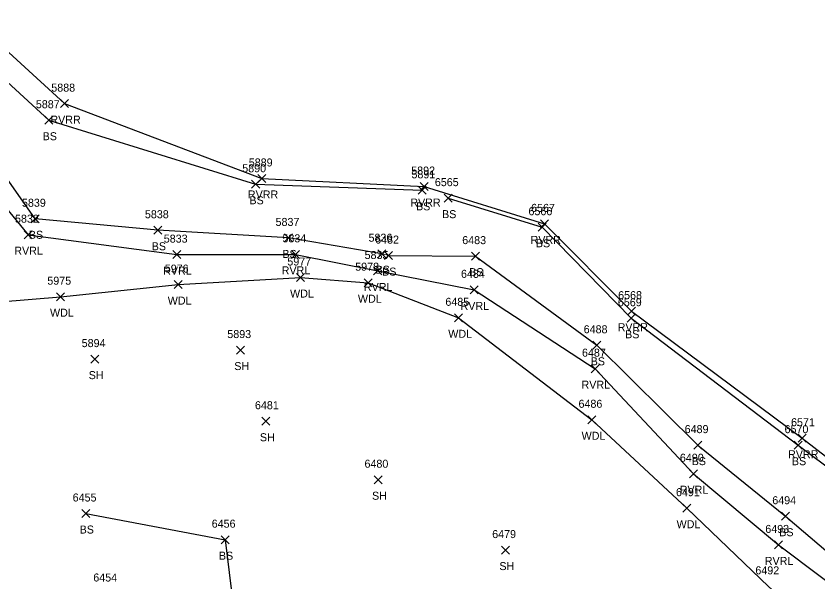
# Model space of a CAD drawing. Extents: x 1588028 to 1589597, y 137576 to 138176.
# Drawn here: x 1588574.1 to 1588774.4, y 138029.2 to 138170.6 of the extents above; entities that cross this region are included whole.
import ezdxf

# ---------------------------------------------------------------- set-up
doc = ezdxf.new("R2010")
doc.units = 0
for name, color, linetype in [('L_A', 7, 'Continuous'), ('L_I', 7, 'Continuous'), ('L_TIC', 7, 'Continuous'), ('LAWA', 7, 'Continuous'), ('LAWE', 7, 'Continuous'), ('LELB', 7, 'Continuous')]:
    doc.layers.add(name, color=color, linetype=linetype)

msp = doc.modelspace()

# ---------------------------------------------------------------- linework, layer by layer
at = {"layer": 'L_TIC'}
for points in [[(1588585.16, 138147.71), (1588587.16, 138149.71)], [(1588587.16, 138147.71), (1588585.16, 138149.71)], [(1588581.3, 138143.56), (1588583.3, 138145.56)], [(1588583.3, 138143.56), (1588581.3, 138145.56)], [(1588634.49, 138129.01), (1588636.49, 138131.01)], [(1588636.49, 138129.01), (1588634.49, 138131.01)], [(1588632.94, 138127.56), (1588634.94, 138129.56)], [(1588634.94, 138127.56), (1588632.94, 138129.56)], [(1588674.55, 138126.05), (1588676.55, 138128.05)], [(1588676.55, 138126.05), (1588674.55, 138128.05)], [(1588675.05, 138126.99), (1588677.05, 138128.99)], [(1588677.05, 138126.99), (1588675.05, 138128.99)], [(1588681.05, 138124.09), (1588683.05, 138126.09)], [(1588683.05, 138124.09), (1588681.05, 138126.09)], [(1588577.85, 138118.94), (1588579.85, 138120.94)], [(1588579.85, 138118.94), (1588577.85, 138120.94)], [(1588608.54, 138116.07), (1588610.54, 138118.07)], [(1588610.54, 138116.07), (1588608.54, 138118.07)], [(1588704.48, 138116.82), (1588706.48, 138118.82)], [(1588706.48, 138116.82), (1588704.48, 138118.82)], [(1588705.09, 138117.66), (1588707.09, 138119.66)], [(1588707.09, 138117.66), (1588705.09, 138119.66)], [(1588576.1, 138114.96), (1588578.1, 138116.96)], [(1588578.1, 138114.96), (1588576.1, 138116.96)], [(1588641.17, 138114.15), (1588643.17, 138116.15)], [(1588643.17, 138114.15), (1588641.17, 138116.15)], [(1588613.25, 138109.98), (1588615.25, 138111.98)], [(1588615.25, 138109.98), (1588613.25, 138111.98)], [(1588642.88, 138110.05), (1588644.88, 138112.05)], [(1588644.88, 138110.05), (1588642.88, 138112.05)], [(1588664.44, 138110.2), (1588666.44, 138112.2)], [(1588666.44, 138110.2), (1588664.44, 138112.2)], [(1588666.09, 138109.74), (1588668.09, 138111.74)], [(1588668.09, 138109.74), (1588666.09, 138111.74)], [(1588687.84, 138109.6), (1588689.84, 138111.6)], [(1588689.84, 138109.6), (1588687.84, 138111.6)], [(1588644.11, 138104.26), (1588646.11, 138106.26)], [(1588646.11, 138104.26), (1588644.11, 138106.26)], [(1588663.41, 138105.89), (1588665.41, 138107.89)], [(1588665.41, 138105.89), (1588663.41, 138107.89)], [(1588613.56, 138102.49), (1588615.56, 138104.49)], [(1588615.56, 138102.49), (1588613.56, 138104.49)], [(1588661.06, 138102.96), (1588663.06, 138104.96)], [(1588663.06, 138102.96), (1588661.06, 138104.96)], [(1588687.53, 138101.18), (1588689.53, 138103.18)], [(1588689.53, 138101.18), (1588687.53, 138103.18)], [(1588584.17, 138099.47), (1588586.17, 138101.47)], [(1588586.17, 138099.47), (1588584.17, 138101.47)], [(1588683.62, 138094.19), (1588685.62, 138096.19)], [(1588685.62, 138094.19), (1588683.62, 138096.19)], [(1588726.76, 138094.08), (1588728.76, 138096.08)], [(1588728.76, 138094.08), (1588726.76, 138096.08)], [(1588726.82, 138095.85), (1588728.82, 138097.85)], [(1588728.82, 138095.85), (1588726.82, 138097.85)], [(1588629.12, 138086.13), (1588631.12, 138088.13)], [(1588631.12, 138086.13), (1588629.12, 138088.13)], [(1588718.17, 138087.33), (1588720.17, 138089.33)], [(1588720.17, 138087.33), (1588718.17, 138089.33)], [(1588592.75, 138083.87), (1588594.75, 138085.87)], [(1588594.75, 138083.87), (1588592.75, 138085.87)], [(1588717.75, 138081.48), (1588719.75, 138083.48)], [(1588719.75, 138081.48), (1588717.75, 138083.48)], [(1588635.5, 138068.35), (1588637.5, 138070.35)], [(1588637.5, 138068.35), (1588635.5, 138070.35)], [(1588716.93, 138068.71), (1588718.93, 138070.71)], [(1588718.93, 138068.71), (1588716.93, 138070.71)], [(1588769.39, 138064.1), (1588771.39, 138066.1)], [(1588771.39, 138064.1), (1588769.39, 138066.1)], [(1588743.4, 138062.38), (1588745.4, 138064.38)], [(1588745.4, 138062.38), (1588743.4, 138064.38)], [(1588768.43, 138062.36), (1588770.43, 138064.36)], [(1588770.43, 138062.36), (1588768.43, 138064.36)], [(1588742.28, 138055.23), (1588744.28, 138057.23)], [(1588744.28, 138055.23), (1588742.28, 138057.23)], [(1588663.51, 138053.73), (1588665.51, 138055.73)], [(1588665.51, 138053.73), (1588663.51, 138055.73)], [(1588740.65, 138046.62), (1588742.65, 138048.62)], [(1588742.65, 138046.62), (1588740.65, 138048.62)], [(1588590.54, 138045.29), (1588592.54, 138047.29)], [(1588592.54, 138045.29), (1588590.54, 138047.29)], [(1588765.27, 138044.61), (1588767.27, 138046.61)], [(1588767.27, 138044.61), (1588765.27, 138046.61)], [(1588625.32, 138038.75), (1588627.32, 138040.75)], [(1588627.32, 138038.75), (1588625.32, 138040.75)], [(1588695.32, 138036.15), (1588697.32, 138038.15)], [(1588697.32, 138036.15), (1588695.32, 138038.15)], [(1588763.53, 138037.44), (1588765.53, 138039.44)], [(1588765.53, 138037.44), (1588763.53, 138039.44)]]:
    msp.add_lwpolyline(points, dxfattribs=at)
at = {"layer": 'LAWA'}
msp.add_lwpolyline([(1588438.89, 138034.8), (1588460.15, 138038.23), (1588480.55, 138035.11), (1588505.29, 138026.54), (1588523.98, 138028.49), (1588536.66, 138053.55), (1588553.84, 138097.83), (1588585.17, 138100.47), (1588614.56, 138103.49), (1588645.11, 138105.26), (1588662.06, 138103.96), (1588684.62, 138095.19), (1588717.93, 138069.71), (1588741.65, 138047.62), (1588762.05, 138028.09), (1588788.28, 138004.54)], dxfattribs=at)
at = {"layer": 'LAWE'}
for points in [[(1588434.56, 138062.89), (1588458.47, 138076.79), (1588495.54, 138110.89), (1588517.72, 138151.17), (1588540.38, 138168.38), (1588562.32, 138170.6), (1588586.16, 138148.71), (1588635.49, 138130.01), (1588676.05, 138127.99), (1588706.09, 138118.66), (1588727.82, 138096.85), (1588770.39, 138065.1), (1588798.8, 138043.18), (1588827.56, 138018.04), (1588869.93, 137975.12), (1588899.99, 137936.94), (1588912.08, 137921.5), (1588926.82, 137898.29), (1588932.86, 137884.09), (1588938.83, 137878.76)], [(1588441.02, 138044.54), (1588465.05, 138060.11), (1588492.43, 138083.39), (1588521.86, 138113.88), (1588530.72, 138143.54), (1588545.57, 138151.23), (1588554.85, 138142.99), (1588577.1, 138115.96), (1588614.25, 138110.98), (1588643.88, 138111.05), (1588664.41, 138106.89), (1588688.53, 138102.18), (1588718.75, 138082.48), (1588743.28, 138056.23), (1588764.53, 138038.44), (1588797.04, 138013.98), (1588814.47, 138001.04), (1588852.47, 137959.37), (1588883.95, 137928.09), (1588897.47, 137912.79), (1588913.44, 137894.45), (1588920.69, 137884.16), (1588921.99, 137878.45)]]:
    msp.add_lwpolyline(points, dxfattribs=at)
at = {"layer": 'LELB'}
for points in [[(1588436.71, 138060.38), (1588458.88, 138076.1), (1588497.26, 138109.57), (1588518.14, 138150.78), (1588541.4, 138166.66), (1588559.34, 138165.64), (1588582.3, 138144.56), (1588633.94, 138128.56), (1588675.55, 138127.05)], [(1588665.44, 138111.2), (1588642.17, 138115.15), (1588609.54, 138117.07), (1588578.85, 138119.94), (1588562.88, 138142.65), (1588547.64, 138155.17), (1588533.27, 138148.8), (1588529.69, 138143.67), (1588525.97, 138129.22), (1588517.34, 138113.35), (1588491.08, 138084.67), (1588470.51, 138067.55), (1588448.25, 138052.11)], [(1588682.05, 138125.09), (1588705.48, 138117.82), (1588727.76, 138095.08), (1588769.43, 138063.36), (1588798.46, 138041.61), (1588826.19, 138016.5), (1588867.28, 137972.84), (1588898.61, 137935.76), (1588911.42, 137921.16), (1588925.66, 137898.09), (1588931.8, 137883.5), (1588937.54, 137876.95)], [(1588667.09, 138110.74), (1588688.84, 138110.6), (1588719.17, 138088.33), (1588744.4, 138063.38), (1588766.27, 138045.61), (1588798.27, 138018.43), (1588815.99, 138001.93), (1588854.1, 137960.89), (1588885.58, 137929.53), (1588899.45, 137912.94)], [(1588591.54, 138046.29), (1588626.32, 138039.75), (1588630.34, 138007.04), (1588626.86, 137991.11), (1588639.77, 137986.11), (1588660.41, 138007.02), (1588678.67, 138013.51), (1588710.59, 137997.46), (1588735.69, 137986.71)]]:
    msp.add_lwpolyline(points, dxfattribs=at)

# ---------------------------------------------------------------- texts
at = {"layer": 'L_A'}
for s, p in [('RVRR', (1588582.67, 138143.71)), ('BS', (1588580.74, 138139.56)), ('RVRR', (1588632, 138125.01)), ('BS', (1588632.38, 138123.56)), ('RVRR', (1588672.56, 138122.99)), ('BS', (1588673.99, 138122.05)), ('BS', (1588680.49, 138120.09)), ('BS', (1588577.29, 138114.94)), ('BS', (1588607.98, 138112.07)), ('RVRR', (1588702.6, 138113.66)), ('BS', (1588703.92, 138112.82)), ('RVRL', (1588573.66, 138110.96)), ('BS', (1588640.61, 138110.15)), ('RVRL', (1588610.82, 138105.98)), ('RVRL', (1588640.44, 138106.05)), ('BS', (1588663.88, 138106.2)), ('BS', (1588665.53, 138105.74)), ('BS', (1588687.28, 138105.6)), ('WDL', (1588642.53, 138100.26)), ('RVRL', (1588660.97, 138101.89)), ('WDL', (1588611.98, 138098.49)), ('WDL', (1588659.48, 138098.96)), ('RVRL', (1588685.1, 138097.18)), ('WDL', (1588582.58, 138095.47)), ('WDL', (1588682.04, 138090.19)), ('RVRR', (1588724.34, 138091.85)), ('BS', (1588726.2, 138090.08)), ('SH', (1588628.6, 138082.13)), ('BS', (1588717.61, 138083.33)), ('SH', (1588592.24, 138079.87)), ('RVRL', (1588715.32, 138077.48)), ('SH', (1588634.99, 138064.35)), ('WDL', (1588715.34, 138064.71)), ('RVRR', (1588766.9, 138060.1)), ('BS', (1588742.84, 138058.38)), ('BS', (1588767.87, 138058.36)), ('RVRL', (1588739.85, 138051.23)), ('SH', (1588663, 138049.73)), ('WDL', (1588739.06, 138042.62)), ('BS', (1588589.98, 138041.29)), ('BS', (1588764.71, 138040.61)), ('BS', (1588624.76, 138034.75)), ('SH', (1588694.81, 138032.15)), ('RVRL', (1588761.09, 138033.44))]:
    msp.add_text(s, height=2, dxfattribs=at).set_placement(p)
at = {"layer": 'L_I'}
for s, p in [('5888', (1588582.9, 138151.71)), ('5887', (1588579.04, 138147.56)), ('5889', (1588632.22, 138133.01)), ('5890', (1588630.59, 138131.56)), ('5892', (1588672.79, 138130.99)), ('5891', (1588672.85, 138130.05)), ('6565', (1588678.69, 138128.09)), ('5839', (1588575.58, 138122.94)), ('5838', (1588606.28, 138120.07)), ('6566', (1588702.07, 138120.82)), ('6567', (1588702.73, 138121.66)), ('5832', (1588573.84, 138118.96)), ('5837', (1588638.91, 138118.15)), ('5833', (1588610.99, 138113.98)), ('5834', (1588640.62, 138114.05)), ('5836', (1588662.13, 138114.2)), ('6482', (1588663.78, 138113.74)), ('6483', (1588685.53, 138113.6)), ('5977', (1588641.85, 138108.26)), ('5835', (1588661.15, 138109.89)), ('5976', (1588611.24, 138106.49)), ('5978', (1588658.8, 138106.96)), ('6484', (1588685.22, 138105.18)), ('5975', (1588581.91, 138103.47)), ('6485', (1588681.32, 138098.19)), ('6569', (1588724.4, 138098.08)), ('6568', (1588724.47, 138099.85)), ('5893', (1588626.86, 138090.13)), ('6488', (1588715.86, 138091.33)), ('5894', (1588590.49, 138087.87)), ('6487', (1588715.44, 138085.48)), ('6481', (1588633.76, 138072.35)), ('6486', (1588714.57, 138072.71)), ('6571', (1588767.65, 138068.1)), ('6489', (1588741.08, 138066.38)), ('6570', (1588766.03, 138066.36)), ('6490', (1588739.89, 138059.23)), ('6480', (1588661.12, 138057.73)), ('6491', (1588738.91, 138050.62)), ('6455', (1588588.24, 138049.29)), ('6494', (1588762.96, 138048.61)), ('6456', (1588622.96, 138042.75)), ('6479', (1588693.01, 138040.15)), ('6493', (1588761.22, 138041.44)), ('6492', (1588758.74, 138031.09)), ('6454', (1588593.39, 138029.3))]:
    msp.add_text(s, height=2, dxfattribs=at).set_placement(p)

doc.saveas('drawing.dxf')
